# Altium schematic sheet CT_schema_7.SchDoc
size 287 x 160 mm
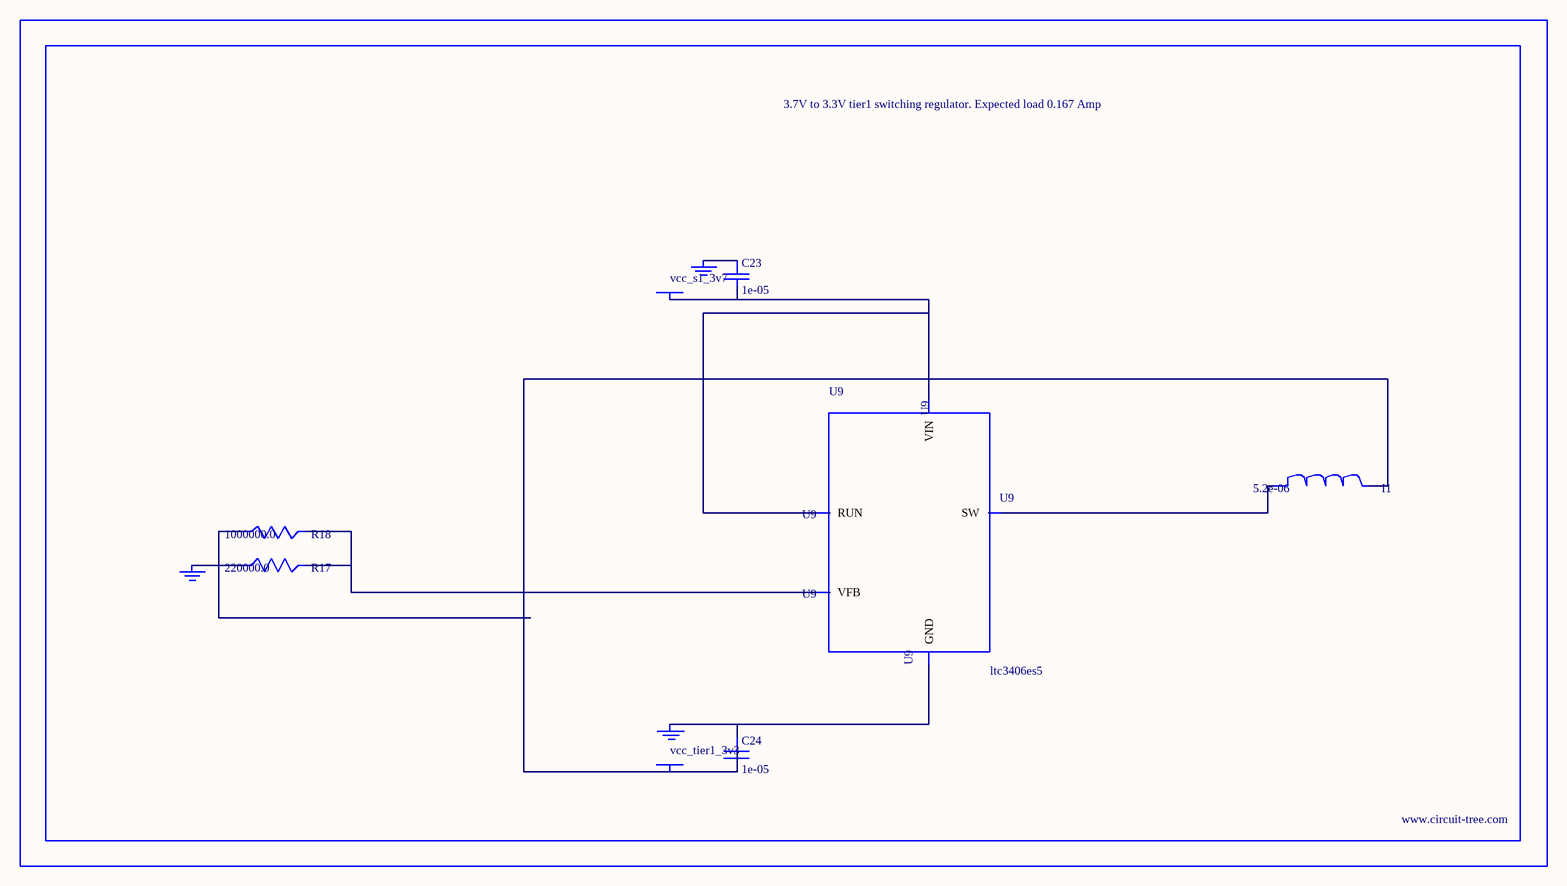
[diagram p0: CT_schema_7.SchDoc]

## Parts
BORDER6  (no value)
C23  1e-05  [C0805]
C24  1e-05  [C0805]
GND_INSTANCE_6_0  (no value)
GND_INSTANCE_6_1  (no value)
GND_INSTANCE_6_2  (no value)
I1  5.2e-06  [DR1040]
POWER_INSTANCE_6_0  vcc_tier1_3v3
POWER_INSTANCE_6_1  vcc_s1_3v7
R17  220000.0  [R0603]
R18  1000000.0  [R0603]
U9  ltc3406es5  [TSOT-23-5]

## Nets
NetC23_1: C23.1 GND_INSTANCE_6_1.0(GND)
NetC23_2: C23.2 POWER_INSTANCE_6_1.0(PWR) U9.1(RUN) U9.4(VIN)
NetC24_1: C24.1 GND_INSTANCE_6_0.0(GND) U9.2(GND)
NetC24_2: C24.2 I1.2 POWER_INSTANCE_6_0.0(PWR) R18.1
NetGND_INSTANCE_6_2_0: GND_INSTANCE_6_2.0(GND) R17.1
NetI1_1: I1.1 U9.3(SW)
NetR17_2: R17.2 R18.2 U9.5(VFB)

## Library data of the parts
BORDER6 = BORDER_PAGE6
C23 C24 = C0805C106K8RACTU
GND_INSTANCE_6_0-GND_INSTANCE_6_2 = GND
I1 = DR1040-5R2-R
POWER_INSTANCE_6_0 POWER_INSTANCE_6_1 = PWR
R17 = RC0603JR-07220KL
R18 = RC0603JR-071ML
